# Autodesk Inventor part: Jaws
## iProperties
Created: 2005-11
Part Number: Jaws
Document SubType Name: Modeling
Designer: Administrator
Manufacturer: Standard
Standards Organization: Custom
Author: Administrator
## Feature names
1. Extrusion1
2. Hole1
3. Chamfer1
4. Chamfer2
5. Extrusion2
6. Extrusion3
